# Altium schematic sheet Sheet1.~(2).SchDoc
size A4
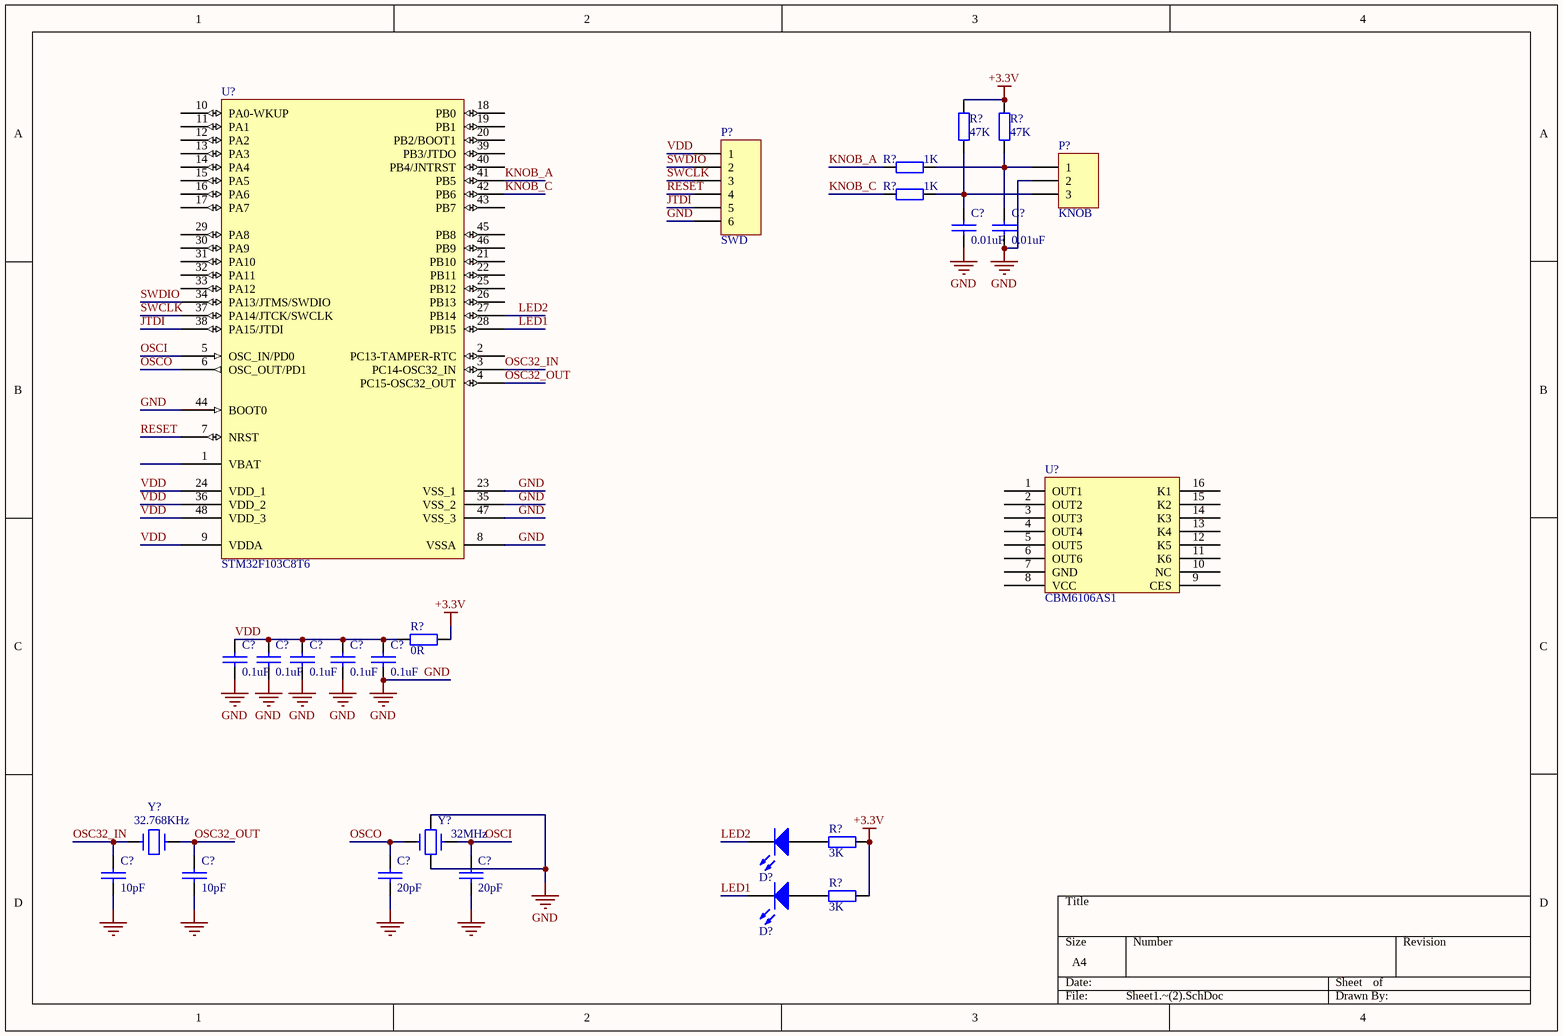
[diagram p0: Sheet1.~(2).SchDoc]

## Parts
(Parts that share a designator on the sheet are numbered #1, #2 ... from top to bottom, then left to right.)
C?#1  0.01uF  [0402C]
C?#2  0.01uF  [0402C]
C?#3  0.1uF  [0402C]
C?#4  0.1uF  [0402C]
C?#5  0.1uF  [0402C]
C?#6  0.1uF  [0402C]
C?#7  0.1uF  [0402C]
C?#8  10pF  [0402C]
C?#9  10pF  [0402C]
C?#10  20pF  [0402C]
C?#11  20pF  [0402C]
D?#1  LED0  [led0603]  (value not drawn)
D?#2  LED0  [led0603]  (value not drawn)
P?#1  SWD  [HDR6X1_B2]
P?#2  KNOB  [HDR3X1_A]
R?#1  value 47K  [0603-1]  (hidden comment: Res1)
R?#2  value 47K  [0603-1]  (hidden comment: Res1)
R?#3  value 1K  [0603-1]  (hidden comment: Res1)
R?#4  value 1K  [0603-1]  (hidden comment: Res1)
R?#5  value 0R  [0402R]  (hidden comment: Res1)
R?#6  value 3K  [0402R]  (hidden comment: Res1)
R?#7  value 3K  [0402R]  (hidden comment: Res1)
U?#1  STM32F103C8T6  [LQFP48_N]
U?#2  CBM6106AS1
Y?#1  32.768KHz  [SMD3215]
Y?#2  32MHz  [Y3225]

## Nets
+3.3V: R?#1.2 R?#2.2 R?#5.2 R?#6.1 R?#7.1
GND: C?#1.2 C?#2.2 C?#3.2 C?#4.2 C?#5.2 C?#6.2 C?#7.2 C?#8.2 C?#9.2 C?#10.2 C?#11.2 P?#1.6 P?#2.2 U?#1.8(VSSA) U?#1.23(VSS_1) U?#1.35(VSS_2) U?#1.44(BOOT0) U?#1.47(VSS_3) Y?#2.2 Y?#2.4
JTDI: P?#1.5 U?#1.38(PA15/JTDI)
KNOB_A: R?#3.1 U?#1.41(PB5)
KNOB_C: R?#4.1 U?#1.42(PB6)
LED1: D?#2.2(K) U?#1.28(PB15)
LED2: D?#1.2(K) U?#1.27(PB14)
OSC32_IN: C?#8.1 U?#1.3(PC14-OSC32_IN) Y?#1.1
OSC32_OUT: C?#9.1 U?#1.4(PC15-OSC32_OUT) Y?#1.2
OSCI: C?#11.1 U?#1.5(OSC_IN/PD0) Y?#2.3
OSCO: C?#10.1 U?#1.6(OSC_OUT/PD1) Y?#2.1
RESET: P?#1.4 U?#1.7(NRST)
SWCLK: P?#1.3 U?#1.37(PA14/JTCK/SWCLK)
SWDIO: P?#1.2 U?#1.34(PA13/JTMS/SWDIO)
VDD: C?#3.1 C?#4.1 C?#5.1 C?#6.1 C?#7.1 P?#1.1 R?#5.1 U?#1.9(VDDA) U?#1.24(VDD_1) U?#1.36(VDD_2) U?#1.48(VDD_3)
NetC?#1_1: C?#1.1 P?#2.3 R?#1.1 R?#4.2
NetC?#2_1: C?#2.1 P?#2.1 R?#2.1 R?#3.2
NetD?#1_1: D?#1.1(A) R?#6.2
NetD?#2_1: D?#2.1(A) R?#7.2

Not connected (* = marked no-connect by the designer): U?#1 1(VBAT) 2(PC13-TAMPER-RTC) 10(PA0-WKUP) 11(PA1) 12(PA2) 13(PA3) 14(PA4) 15(PA5) 16(PA6) 17(PA7) 18(PB0) 19(PB1) 20(PB2/BOOT1) 21(PB10) 22(PB11) 25(PB12) 26(PB13) 29(PA8) 30(PA9) 31(PA10) 32(PA11) 33(PA12) 39(PB3/JTDO) 40(PB4/JNTRST) 43(PB7) 45(PB8) 46(PB9); U?#2 1(OUT1) 2(OUT2) 3(OUT3) 4(OUT4) 5(OUT5) 6(OUT6) 7(GND) 8(VCC) 9(CES) 10(NC) 11(K6) 12(K5) 13(K4) 14(K3) 15(K2) 16(K1)

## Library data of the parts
C?#1-C?#11 = CAP: Capacitor
D?#1 D?#2 = LED0: 发光二极管
P?#1 = Header 6: 接插件
P?#2 = Header 3: 接插件
R?#1-R?#7 = Res1: 贴片电阻
U?#1 = STM32F103C8T6: STM32 ARM-based 32-bit MCU with 64 Kbytes Flash, 48-pin LQFP, Industrial Temperature
Y?#1 = CRYSTAL
Y?#2 = CRYSTAL1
